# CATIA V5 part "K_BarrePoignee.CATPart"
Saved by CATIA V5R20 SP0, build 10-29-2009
Part number: barre_poignee_volume
Bounding box of the stored display mesh (mm): x -396.739 to -25.008, y -110 to 110, z 975.008 to 1294.971
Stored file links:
  G:\Khaled_CFAO_2011\ST2M\ST2M_GR1\cdurantin\cdurantin\Khaled\CAD_ThinkMOTION\K_BarrePoignee.CATPart
  C:\Documents and Settings\cdurantin\Bureau\cdurantin\caddy.CATProduct
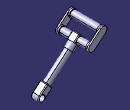
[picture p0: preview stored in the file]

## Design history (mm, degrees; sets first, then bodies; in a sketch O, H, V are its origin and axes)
Parameters
  `longueur poignee` = 100 mm
  `largeur poignée` = 200 mm
External parameters (linked from other documents)
  `External.diamètre des barres` = 40 mm
  `External.Surepaisseur du tube` = 10 mm
Set1
  Line1 to Line4: linked copy from another document
Body1 "raccord_poignee" (main body)
  Sketch1 on zx-plane, origin (0, 0, 0), H (-1, 0, 0), V (0, 0, 1)
    reference projected point E1 (50, 1000) from Line1
    circle A1 centre (50, 1000) radius 20
    arc A2 centre (50, 1000) radius 25 from (33.9303, 1019.1511) to (66.0697, 980.8489) ccw
    reference projected line E2 (356.4178, 1257.115) -> (50, 1000) from Line2
    line L1 (33.9303, 1019.1511) -> (87.5534, 1064.1462)
    line L2 (87.5534, 1064.1462) -> (119.6928, 1025.844)
    line L3 (119.6928, 1025.844) -> (66.0697, 980.8489)
    radius A1 = 20 {= `External.diamètre des barres` /2}
    radius A2 = 25 {= `External.diamètre des barres` /2+`External.Surepaisseur du tube` /2}
    length L2 = 50 {= `External.diamètre des barres` +`External.Surepaisseur du tube`}
    distance L3 E2 = 25 {= (`External.diamètre des barres` +`External.Surepaisseur du tube` )/2}
    distance L2 A1 = 50 {= (`External.diamètre des barres` +`External.Surepaisseur du tube` )}
    concentricity: E1 A1, A2 A1
    parallelism: L1 E2
    perpendicularity: L2 E2
  Pad1: profile Sketch1, direction (0, 1, 0), length 25 {= (`External.diamètre des barres` +`External.Surepaisseur du tube` )/2}, mirrored extent
  Sketch2 on face of Pad1 from Sketch1.L2, origin (-203.4068, -7.8881, 926.0775), H (0.6428, 0, 0.766), V (0, 1, 0)
    point P1 (155.2359, 7.8881)
    reference projected line E1 (-22.973, 32.8881) -> (27.027, 32.8881) from edge [face of Pad1 from Sketch1.L2 | end face of Pad1]
    reference projected line E2 (180.2359, -17.1119) -> (180.2359, 32.8881) from edge [face of Pad1 from Sketch1.L1 | face of Pad1 from Sketch1.L2]
    distance P1 E1 = 25 {= (`External.diamètre des barres` +`External.Surepaisseur du tube` )/2}
    distance P1 E2 = 25 {= (`External.diamètre des barres` +`External.Surepaisseur du tube` )/2}
  Hole1: placed by Sketch2, at (-103.6231, 0, 1044.9951) direction (0.766, 0, -0.6428), diameter 40 {= `External.diamètre des barres`}, depth 40 {= `External.diamètre des barres`}
  Fillet1: radius 5, on edge [face of Pad1 from Sketch1.L1 | end face of Pad1]; edge [face of Pad1 from Sketch1.L2 | end face of Pad1]; edge [start face of Pad1 | face of Pad1 from Sketch1.L1]; edge [face of Pad1 from Sketch1.L1 | face of Pad1 from Sketch1.L2]; edge [start face of Pad1 | face of Pad1 from Sketch1.L2]; edge [face of Pad1 from Sketch1.L2 | face of Pad1 from Sketch1.L3]
Body2 "barre_poignee"
  Sketch3 on zx-plane, origin (0, 0, 0), H (-1, 0, 0), V (0, 0, 1)
    reference projected line E1 (356.4178, 1257.115) -> (50, 1000) from Line2
    line L1 (60.1256, 1034.6045) -> (266.9576, 1208.1572)
    line L2 (266.9576, 1208.1572) -> (279.8133, 1192.8363)
    line L3 (279.8133, 1192.8363) -> (72.9813, 1019.2836)
    line L4 (72.9813, 1019.2836) -> (60.1256, 1034.6045)
    reference projected point E2 (50, 1000) from Line1
    reference projected point E3 (356.4178, 1257.115) from Line3
    distance L4 E2 = 30 {= (`External.diamètre des barres` )/2+`External.Surepaisseur du tube`}
    distance E3 L2 = 100 {= `longueur poignee`}
    distance L1 L3 = 20 {= `External.diamètre des barres` /2}
    distance L3 E1 = 0
    parallelism: L1 E1, L4 L2
    perpendicularity: L2 E1
  Shaft1: profile Sketch3, axis Sketch3.L3, angle 360
Body3 "poignee"
  Sketch4 on face of Shaft1 from Sketch3.L2, origin (-751.5584, 0, 630.6324), H (0, -1, 0), V (0.6428, 0, 0.766)
    circle A1 centre (0, 733.9051) radius 25
    reference projected circle E1 centre (0, 733.9051) radius 20 from edge [face of Shaft1 from Sketch3.L1 | face of Shaft1 from Sketch3.L2]
    circle A2 centre (0, 733.9051) radius 20
    radius A1 = 25 {= (`External.diamètre des barres` +`External.Surepaisseur du tube` )/2}
    radius A2 = 20 {= `External.diamètre des barres` /2}
    concentricity: E1 A1, A2 A1
  Pad2: profile Sketch4, direction (0.766, 0, -0.6428), length 40 {= `External.diamètre des barres`}
  Sketch5 on start face of Pad2, origin (-751.5584, 0, 630.6324), H (0, -1, 0), V (0.6428, 0, 0.766)
    line L1 (-25, 758.9051) -> (25, 758.9051)
    line L2 (25, 758.9051) -> (25, 708.9051)
    line L3 (25, 708.9051) -> (-25, 708.9051)
    line L4 (-25, 708.9051) -> (-25, 758.9051)
    reference projected point E1 (25, 733.9051) from Line4
    reference projected point E2 (-25, 733.9051) from Line2
    length L1 = 50 {= `External.diamètre des barres` +`External.Surepaisseur du tube`}
    length L2 = 50 {= `External.diamètre des barres` +`External.Surepaisseur du tube`}
    distance L1 E1 = 25 {= (`External.diamètre des barres` +`External.Surepaisseur du tube` )/2}
    distance L2 E2 = 50 {= `External.diamètre des barres` +`External.Surepaisseur du tube`}
    horizontal: L1 H, L3 H
    vertical: L2 V, L4 V
  Pad3: profile Sketch5, direction (-0.766, 0, 0.6428), length 50 {= `External.diamètre des barres` +`External.Surepaisseur du tube`}
  Sketch6 on face of Pad3 from Sketch5.L4, origin (-306.3424, 25, 1008.2604), H (1, 0, 0), V (0, 0, -1)
    point P1 (7.378, -200.6455)
    reference projected line E1 (108.9402, -82.7896) -> (70.638, -114.9289) from edge [face of Pad3 from Sketch5.L3 | face of Pad3 from Sketch5.L4]
    reference projected line E2 (-94.1842, -118.5015) -> (-126.3236, -80.1993) from edge [face of Pad3 from Sketch5.L4 | end face of Pad3]
    distance P1 E1 = 25 {= (`External.diamètre des barres` +`External.Surepaisseur du tube` )/2}
    distance P1 E2 = 25 {= (`External.diamètre des barres` +`External.Surepaisseur du tube` )/2}
  Hole2: placed by Sketch6, at (-298.9644, 25, 1208.906) direction (0, -1, 0), diameter 40 {= `External.diamètre des barres`}, through (limit type 6)
  Fillet2: radius 5, on edge [face of Pad3 from Sketch5.L4 | face of Pad3 from Sketch5.L1]; edge [face of Pad3 from Sketch5.L4 | end face of Pad3]; edge [face of Pad3 from Sketch5.L3 | face of Pad3 from Sketch5.L4]; edge [face of Pad3 from Sketch5.L3 | end face of Pad3]; edge [face of Pad3 from Sketch5.L2 | end face of Pad3]; edge [face of Pad3 from Sketch5.L1 | end face of Pad3]; edge [face of Pad3 from Sketch5.L1 | face of Pad3 from Sketch5.L2]; edge [face of Pad3 from Sketch5.L2 | face of Pad3 from Sketch5.L3]
  Sketch7 on zx-plane, origin (0, 0, 0), H (-1, 0, 0), V (0, 0, 1)
    circle A1 centre (298.9644, 1208.906) radius 20
    reference projected point E1 (298.9644, 1208.906) from axis of face of Hole2
    radius A1 = 20 {= `External.diamètre des barres` /2}
    concentricity: E1 A1
  Pad4: profile Sketch7, direction (0, 1, 0), length 100 {= `largeur poignée` /2}, mirrored extent
  Sketch8 on end face of Pad4, origin (0, 100, 0), H (-1, 0, 0), V (0, 0, 1)
    circle A1 centre (298.9644, 1208.906) radius 25
    reference projected circle E1 centre (298.9644, 1208.906) radius 20 from edge [face of Pad4 from Sketch7.A1 | end face of Pad4]
    circle A2 centre (298.9644, 1208.906) radius 20
    radius A2 = 20 {= `External.diamètre des barres` /2}
    radius A1 = 25 {= (`External.diamètre des barres` +`External.Surepaisseur du tube` )/2}
    concentricity: E1 A1, A2 A1
  Pad5: profile Sketch8, direction (0, -1, 0), length 10 {= `External.Surepaisseur du tube`}
  Sketch9 on zx-plane, origin (0, 0, 0), H (-1, 0, 0), V (0, 0, 1)
    reference projected point E1 (356.4178, 1257.115) from Line3
    circle A1 centre (371.7387, 1269.9708) radius 20
    point P1 (371.7387, 1269.9708)
    reference projected line E2 (257.937, 1174.4799) -> (-48.4808, 917.3648) from Line2
    distance P1 E2 = 0
    radius A1 = 20 {= `External.diamètre des barres` /2}
    coincidence: A1 E1
  Pad6: profile Sketch9, direction (0, 1, 0), length 100 {= `largeur poignée` /2}, mirrored extent
  RectPattern1: of Pad5, direction 1 instances 2, spacing 190 {= `largeur poignée` -`External.Surepaisseur du tube`}, along axis of face of Pad4 from Sketch7.A1, direction 2 instances 2 {= 2}, spacing 95 {= `largeur poignée` /2-5mm}, along Line2 reversed, Nu 2
  Sketch10 on face of RectPattern1, origin (0, 100, 0), H (-1, 0, 0), V (0, 0, 1)
    reference projected line E1 (356.4178, 1257.115) -> (50, 1000) from Line2
    construction line L1 (298.9644, 1208.906) -> (371.7387, 1269.9708)
    point P3 (298.9644, 1208.906)
    line L2 (282.8948, 1228.0571) -> (355.669, 1289.1219)
    line L3 (387.8084, 1250.8197) -> (315.0341, 1189.7549)
    arc A1 centre (371.7387, 1269.9708) radius 25 from (355.669, 1289.1219) to (387.8084, 1250.8197) cw
    arc A2 centre (298.9644, 1208.906) radius 25 from (315.0341, 1189.7549) to (282.8948, 1228.0571) cw
    reference projected circle E2 centre (298.9644, 1208.906) radius 20 from face of Pad4 from Sketch7.A1
    reference projected circle E3 centre (371.7387, 1269.9708) radius 20 from face of Pad6 from Sketch9.A1
    distance L1 L2 = 25 {= (`External.diamètre des barres` +`External.Surepaisseur du tube` )/2}
    coincidence: P3 E1
    parallelism: L1 E1
    tangency: A1 L2, A2 L2, A1 L3, A2 L3
    concentricity: E2 A2, E3 A1
  Pad7: profile Sketch10, direction (0, 1, 0), length 10 {= `External.Surepaisseur du tube`}
  RectPattern2: of Pad7, direction 1 instances 2, spacing 210 {= `largeur poignée` +`External.Surepaisseur du tube`}, along axis of face of Pad4 from Sketch7.A1 reversed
